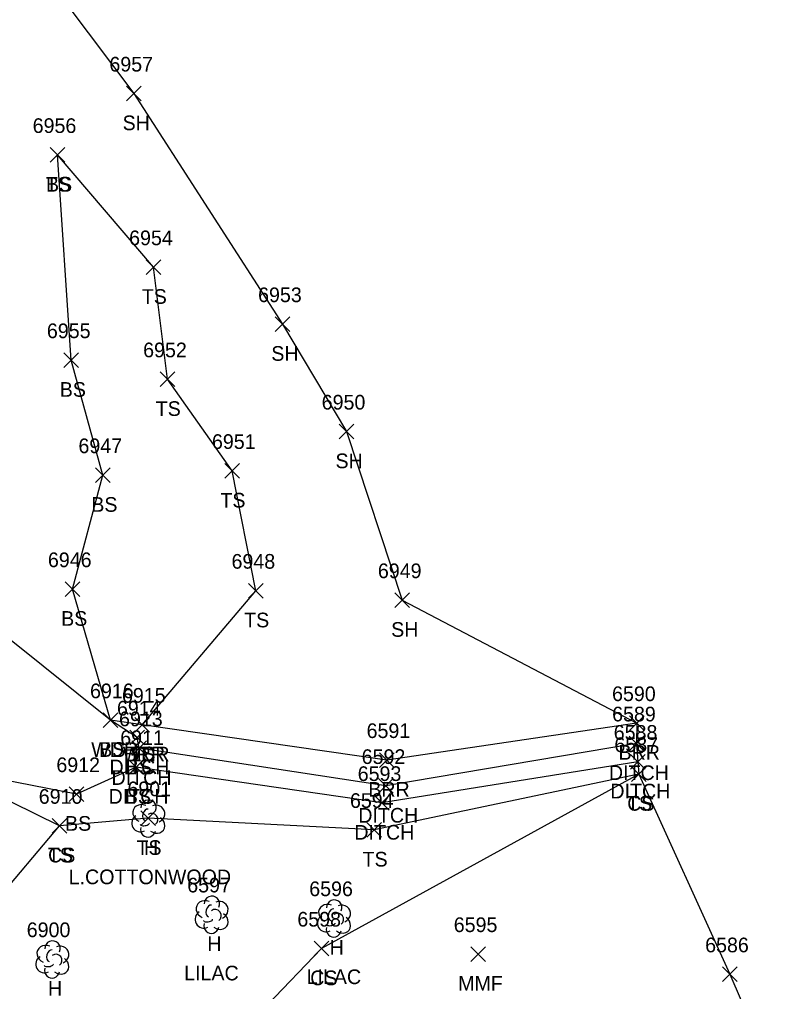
# Model space of a CAD drawing. Extents: x 1439173 to 1457902, y 641926 to 659889.
# Drawn here: x 1448918.5 to 1449022.8, y 643813.5 to 643946.2 of the extents above; entities that cross this region are included whole.
import ezdxf

# ---------------------------------------------------------------- set-up
doc = ezdxf.new("R2010")
doc.units = 0
for name, color, linetype in [('D_A', 7, 'Continuous'), ('D_I', 7, 'Continuous'), ('D_TIC', 7, 'Continuous'), ('DD', 7, 'Continuous'), ('L_A', 7, 'Continuous'), ('L_C', 7, 'Continuous'), ('L_I', 7, 'Continuous'), ('L_TIC', 7, 'Continuous'), ('LABL', 7, 'Continuous'), ('LAWA', 7, 'Continuous'), ('LELB', 7, 'Continuous'), ('LSOGP', 7, 'Continuous'), ('LTD', 7, 'Continuous')]:
    doc.layers.add(name, color=color, linetype=linetype)

msp = doc.modelspace()

# ---------------------------------------------------------------- linework, layer by layer
at = {"layer": 'D_TIC'}
for points in [[(1448933.52, 643847.19), (1448935.52, 643849.19)], [(1448935.52, 643847.19), (1448933.52, 643849.19)], [(1448933.8, 643845.74), (1448935.8, 643847.74)], [(1448935.8, 643845.74), (1448933.8, 643847.74)], [(1449001.59, 643846.4), (1449003.59, 643848.4)], [(1449003.59, 643846.4), (1449001.59, 643848.4)], [(1448933.39, 643843.17), (1448935.39, 643845.17)], [(1448935.39, 643843.17), (1448933.39, 643845.17)], [(1449001.79, 643843.89), (1449003.79, 643845.89)], [(1449003.79, 643843.89), (1449001.79, 643845.89)], [(1448967.43, 643840.59), (1448969.43, 643842.59)], [(1448969.43, 643840.59), (1448967.43, 643842.59)], [(1448966.89, 643838.27), (1448968.89, 643840.27)], [(1448968.89, 643838.27), (1448966.89, 643840.27)]]:
    msp.add_lwpolyline(points, dxfattribs=at)
at = {"layer": 'DD'}
for points in [[(1449002.59, 643847.4), (1448968.43, 643841.59), (1448934.8, 643846.74), (1448934.52, 643848.19)], [(1449002.79, 643844.89), (1448967.89, 643839.27), (1448934.39, 643844.17)]]:
    msp.add_lwpolyline(points, dxfattribs=at)
at = {"layer": 'L_TIC'}
for points in [[(1448933.05, 643935.05), (1448935.05, 643937.05)], [(1448935.05, 643935.05), (1448933.05, 643937.05)], [(1448922.65, 643926.67), (1448924.65, 643928.67)], [(1448924.65, 643926.67), (1448922.65, 643928.67)], [(1448922.65, 643926.67), (1448924.65, 643928.67)], [(1448924.65, 643926.67), (1448922.65, 643928.67)], [(1448935.74, 643911.36), (1448937.74, 643913.36)], [(1448937.74, 643911.36), (1448935.74, 643913.36)], [(1448953.32, 643903.59), (1448955.32, 643905.59)], [(1448955.32, 643903.59), (1448953.32, 643905.59)], [(1448924.53, 643898.68), (1448926.53, 643900.68)], [(1448926.53, 643898.68), (1448924.53, 643900.68)], [(1448937.64, 643896.07), (1448939.64, 643898.07)], [(1448939.64, 643896.07), (1448937.64, 643898.07)], [(1448962.07, 643888.94), (1448964.07, 643890.94)], [(1448964.07, 643888.94), (1448962.07, 643890.94)], [(1448928.83, 643882.99), (1448930.83, 643884.99)], [(1448930.83, 643882.99), (1448928.83, 643884.99)], [(1448946.46, 643883.57), (1448948.46, 643885.57)], [(1448948.46, 643883.57), (1448946.46, 643885.57)], [(1448924.72, 643867.44), (1448926.72, 643869.44)], [(1448926.72, 643867.44), (1448924.72, 643869.44)], [(1448949.7, 643867.23), (1448951.7, 643869.23)], [(1448951.7, 643867.23), (1448949.7, 643869.23)], [(1448969.66, 643865.94), (1448971.66, 643867.94)], [(1448971.66, 643865.94), (1448969.66, 643867.94)], [(1448929.89, 643849.56), (1448931.89, 643851.56)], [(1448931.89, 643849.56), (1448929.89, 643851.56)], [(1448929.89, 643849.56), (1448931.89, 643851.56)], [(1448931.89, 643849.56), (1448929.89, 643851.56)], [(1448934.19, 643848.95), (1448936.19, 643850.95)], [(1448936.19, 643848.95), (1448934.19, 643850.95)], [(1448934.19, 643848.95), (1448936.19, 643850.95)], [(1448936.19, 643848.95), (1448934.19, 643850.95)], [(1448934.19, 643848.95), (1448936.19, 643850.95)], [(1448936.19, 643848.95), (1448934.19, 643850.95)], [(1449001.65, 643849.17), (1449003.65, 643851.17)], [(1449003.65, 643849.17), (1449001.65, 643851.17)], [(1448933.52, 643847.19), (1448935.52, 643849.19)], [(1448935.52, 643847.19), (1448933.52, 643849.19)], [(1448967.54, 643844.13), (1448969.54, 643846.13)], [(1448969.54, 643844.13), (1448967.54, 643846.13)], [(1448933.39, 643843.17), (1448935.39, 643845.17)], [(1448935.39, 643843.17), (1448933.39, 643845.17)], [(1449001.89, 643842.22), (1449003.89, 643844.22)], [(1449003.89, 643842.22), (1449001.89, 643844.22)], [(1449001.89, 643842.22), (1449003.89, 643844.22)], [(1449003.89, 643842.22), (1449001.89, 643844.22)], [(1448925.25, 643839.48), (1448927.25, 643841.48)], [(1448927.25, 643839.48), (1448925.25, 643841.48)], [(1448935.02, 643836.19), (1448937.02, 643838.19)], [(1448937.02, 643836.19), (1448935.02, 643838.19)], [(1448922.94, 643835.16), (1448924.94, 643837.16)], [(1448924.94, 643835.16), (1448922.94, 643837.16)], [(1448922.94, 643835.16), (1448924.94, 643837.16)], [(1448924.94, 643835.16), (1448922.94, 643837.16)], [(1448965.84, 643834.6), (1448967.84, 643836.6)], [(1448967.84, 643834.6), (1448965.84, 643836.6)], [(1448958.67, 643818.41), (1448960.67, 643820.41)], [(1448960.67, 643818.41), (1448958.67, 643820.41)], [(1448979.99, 643817.66), (1448981.99, 643819.66)], [(1448981.99, 643817.66), (1448979.99, 643819.66)], [(1449014.32, 643814.9), (1449016.32, 643816.9)], [(1449016.32, 643814.9), (1449014.32, 643816.9)]]:
    msp.add_lwpolyline(points, dxfattribs=at)
at = {"layer": 'LABL'}
msp.add_lwpolyline([(1449002.65, 643850.17), (1448968.54, 643845.13), (1448935.19, 643849.95)], dxfattribs=at)
at = {"layer": 'LAWA'}
msp.add_lwpolyline([(1448935.19, 643849.95), (1448930.89, 643850.56), (1448912.47, 643865.31), (1448901.69, 643872.66), (1448893.6, 643872.01), (1448887.66, 643878.9), (1448880.15, 643880.34), (1448877.43, 643885.56), (1448873.12, 643888.69), (1448872.18, 643891.06), (1448868.85, 643895.5), (1448865.46, 643900.53), (1448866.99, 643904.37), (1448875.78, 643920.4), (1448875.62, 643935.58), (1448881.79, 643957.41), (1448868.1, 643977.7), (1448859.21, 644002.85), (1448858.88, 644027.76), (1448856.91, 644066.77)], dxfattribs=at)
at = {"layer": 'LELB'}
for points in [[(1448934.52, 643848.19), (1448930.89, 643850.56), (1448925.72, 643868.44), (1448929.83, 643883.99), (1448925.53, 643899.68), (1448923.65, 643927.67)], [(1448935.19, 643849.95), (1448950.7, 643868.23), (1448947.46, 643884.57), (1448938.64, 643897.07), (1448936.74, 643912.36), (1448923.65, 643927.67)], [(1448934.39, 643844.17), (1448926.25, 643840.48), (1448907.86, 643844.08), (1448898.14, 643842.94), (1448892.2, 643837.36)], [(1449002.89, 643843.22), (1448966.84, 643835.6), (1448936.02, 643837.19), (1448923.94, 643836.16), (1448907.86, 643844.08), (1448900.34, 643838.29), (1448899.79, 643830.63), (1448893.68, 643829.16)], [(1449002.89, 643843.22), (1448959.67, 643819.41), (1448944.82, 643803.96), (1448938.16, 643798.4)], [(1448895.29, 643770.7), (1448906.9, 643793.87), (1448905.19, 643812.2), (1448914.92, 643825.49), (1448923.94, 643836.16)]]:
    msp.add_lwpolyline(points, dxfattribs=at)
at = {"layer": 'LSOGP'}
msp.add_lwpolyline([(1448856.91, 644066.77), (1448858.88, 644027.77), (1448883.72, 643997.52), (1448895.03, 643979.77), (1448895.93, 643978.85), (1448899.57, 643975.95), (1448900.3, 643975.15), (1448918.59, 643956.71), (1448934.05, 643936.05), (1448954.32, 643904.59), (1448963.08, 643889.95), (1448970.66, 643866.94), (1449002.65, 643850.17), (1449002.59, 643847.4), (1449002.79, 643844.89), (1449002.89, 643843.22), (1449015.32, 643815.9), (1449022.77, 643798.58)], dxfattribs=at)
at = {"layer": 'LTD'}
for p, q in [((1448936.02, 643837.19), (1448936.02, 643837.19)), ((1448936.02, 643837.19), (1448936.02, 643837.19)), ((1448944.65, 643824.07), (1448944.65, 643824.07)), ((1448944.65, 643824.07), (1448944.65, 643824.07)), ((1448961.34, 643823.56), (1448961.34, 643823.56)), ((1448961.34, 643823.56), (1448961.34, 643823.56)), ((1448922.94, 643817.97), (1448922.94, 643817.97)), ((1448922.94, 643817.97), (1448922.94, 643817.97))]:
    msp.add_line(p, q, dxfattribs=at)
for centre in [(1448936.07, 643838.63), (1448944.7, 643825.51), (1448961.39, 643825), (1448922.99, 643819.41)]:
    msp.add_arc(centre, 1.05, 335.5272, 180.9563, dxfattribs=at)
for centre, major_axis, ratio, start_param, end_param in [((1448935.23, 643837.86), (1.21, -0.51), 0.895232, 1.570796, 4.712389), ((1448935.81, 643837.65), (-0.208, -0.792), 0.645439, 3.141593, 6.283185), ((1448937.06, 643837.78), (-1.14, -0.48), 0.949671, 1.570796, 4.712389), ((1448934.94, 643836.49), (0.58, -1.04), 0.959034, 3.141593, 6.283185), ((1448936.52, 643837.03), (-0.5, 0.667), 0.989748, 3.141593, 6.283185), ((1448937.02, 643836.36), (-1.09, 0.79), 0.841452, 1.570796, 4.712389), ((1448936.02, 643835.69), (0.26, 1.06), 0.942809, 1.570796, 4.712389), ((1448935.56, 643836.44), (-0.625, -0.083), 0.423636, 0, 3.141593), ((1448943.86, 643824.74), (1.21, -0.51), 0.895232, 1.570796, 4.712389), ((1448944.44, 643824.53), (-0.208, -0.792), 0.645439, 3.141593, 6.283185), ((1448945.69, 643824.66), (-1.14, -0.48), 0.949671, 1.570796, 4.712389), ((1448960.55, 643824.23), (1.21, -0.51), 0.895232, 1.570796, 4.712389), ((1448962.38, 643824.15), (-1.14, -0.48), 0.949671, 1.570796, 4.712389), ((1448943.57, 643823.37), (0.58, -1.04), 0.959034, 3.141593, 6.283185), ((1448945.15, 643823.91), (-0.5, 0.667), 0.989748, 3.141593, 6.283185), ((1448945.65, 643823.24), (-1.09, 0.79), 0.841452, 1.570796, 4.712389), ((1448960.26, 643822.85), (0.58, -1.04), 0.959034, 3.141593, 6.283185), ((1448961.13, 643824.02), (-0.208, -0.792), 0.645439, 3.141593, 6.283185), ((1448961.84, 643823.4), (-0.5, 0.667), 0.989748, 3.141593, 6.283185), ((1448962.34, 643822.73), (-1.09, 0.79), 0.841452, 1.570796, 4.712389), ((1448944.65, 643822.57), (0.26, 1.06), 0.942809, 1.570796, 4.712389), ((1448944.19, 643823.32), (-0.625, -0.083), 0.423636, 0, 3.141593), ((1448961.34, 643822.06), (0.26, 1.06), 0.942809, 1.570796, 4.712389), ((1448960.88, 643822.81), (-0.625, -0.083), 0.423636, 0, 3.141593), ((1448922.15, 643818.64), (1.21, -0.51), 0.895232, 1.570796, 4.712389), ((1448923.98, 643818.56), (-1.14, -0.48), 0.949671, 1.570796, 4.712389), ((1448921.86, 643817.26), (0.58, -1.04), 0.959034, 3.141593, 6.283185), ((1448922.73, 643818.43), (-0.208, -0.792), 0.645439, 3.141593, 6.283185), ((1448923.44, 643817.81), (-0.5, 0.667), 0.989748, 3.141593, 6.283185), ((1448922.48, 643817.22), (-0.625, -0.083), 0.423636, 0, 3.141593), ((1448923.94, 643817.14), (-1.09, 0.79), 0.841452, 1.570796, 4.712389), ((1448922.94, 643816.47), (0.26, 1.06), 0.942809, 1.570796, 4.712389)]:
    msp.add_ellipse(centre, major_axis=major_axis, ratio=ratio, start_param=start_param, end_param=end_param, dxfattribs=at)

# ---------------------------------------------------------------- texts
at = {"layer": 'D_A'}
for p in [(1448930.75, 643843.19), (1448931.03, 643841.74), (1448998.83, 643842.4), (1448930.63, 643839.17), (1448999.03, 643839.89), (1448964.67, 643836.59), (1448964.13, 643834.27)]:
    msp.add_text('DITCH', height=2, dxfattribs=at).set_placement(p)
at = {"layer": 'D_I'}
for s, p in [('6914', (1448931.77, 643851.19)), ('6913', (1448932.06, 643849.74)), ('6589', (1448999.27, 643850.4)), ('6911', (1448932.22, 643847.17)), ('6588', (1448999.49, 643847.89)), ('6592', (1448965.13, 643844.59)), ('6593', (1448964.59, 643842.27))]:
    msp.add_text(s, height=2, dxfattribs=at).set_placement(p)
at = {"layer": 'L_A'}
for s, p in [('SH', (1448932.54, 643931.05)), ('TS', (1448922.06, 643922.67)), ('BS', (1448922.09, 643922.67)), ('TS', (1448935.15, 643907.36)), ('SH', (1448952.81, 643899.59)), ('BS', (1448923.97, 643894.68)), ('TS', (1448937.05, 643892.07)), ('SH', (1448961.56, 643884.94)), ('BS', (1448928.27, 643878.99)), ('TS', (1448945.87, 643879.57)), ('BS', (1448924.16, 643863.44)), ('TS', (1448949.11, 643863.23)), ('SH', (1448969.15, 643861.94)), ('WDR', (1448928.26, 643845.56)), ('BS', (1448929.34, 643845.56)), ('WDR', (1448932.55, 643844.95)), ('BRR', (1448932.68, 643844.95)), ('TS', (1448933.6, 643844.95)), ('BRR', (1449000.14, 643845.17)), ('BS', (1448932.96, 643843.19)), ('BS', (1448932.84, 643839.17)), ('BRR', (1448966.03, 643840.13)), ('TS', (1449001.3, 643838.22)), ('CS', (1449001.33, 643838.22)), ('BS', (1448924.69, 643835.48)), ('TS', (1448934.43, 643832.19)), ('H', (1448935.45, 643832.19)), ('TS', (1448922.35, 643831.16)), ('CS', (1448922.38, 643831.16)), ('TS', (1448965.25, 643830.6)), ('H', (1448944.09, 643819.07)), ('H', (1448960.77, 643818.56)), ('CS', (1448958.11, 643814.41)), ('MMF', (1448978.28, 643813.66)), ('H', (1448922.37, 643812.97))]:
    msp.add_text(s, height=2, dxfattribs=at).set_placement(p)
at = {"layer": 'L_C'}
for s, p in [('L.COTTONWOOD', (1448925.19, 643828.19)), ('LILAC', (1448940.93, 643815.07)), ('LILAC', (1448957.62, 643814.56))]:
    msp.add_text(s, height=2, dxfattribs=at).set_placement(p)
at = {"layer": 'L_I'}
for s, p in [('6957', (1448930.74, 643939.05)), ('6956', (1448920.28, 643930.67)), ('6956', (1448920.28, 643930.67)), ('6954', (1448933.43, 643915.36)), ('6953', (1448951.01, 643907.59)), ('6955', (1448922.22, 643902.68)), ('6952', (1448935.34, 643900.07)), ('6950', (1448959.68, 643892.94)), ('6947', (1448926.52, 643886.99)), ('6951', (1448944.72, 643887.57)), ('6946', (1448922.36, 643871.44)), ('6948', (1448947.39, 643871.23)), ('6949', (1448967.34, 643869.94)), ('6916', (1448928.1, 643853.56)), ('6916', (1448928.1, 643853.56)), ('6915', (1448932.45, 643852.95)), ('6915', (1448932.45, 643852.95)), ('6915', (1448932.45, 643852.95)), ('6590', (1448999.26, 643853.17)), ('6914', (1448931.77, 643851.19)), ('6591', (1448965.8, 643848.13)), ('6911', (1448932.22, 643847.17)), ('6587', (1448999.58, 643846.22)), ('6587', (1448999.58, 643846.22)), ('6912', (1448923.51, 643843.48)), ('6901', (1448933.2, 643840.19)), ('6901', (1448933.2, 643840.19)), ('6910', (1448921.11, 643839.16)), ('6910', (1448921.11, 643839.16)), ('6594', (1448963.53, 643838.6)), ('6597', (1448941.35, 643827.07)), ('6596', (1448957.98, 643826.56)), ('6598', (1448956.36, 643822.41)), ('6595', (1448977.68, 643821.66)), ('6900', (1448919.47, 643820.97)), ('6586', (1449011.95, 643818.9))]:
    msp.add_text(s, height=2, dxfattribs=at).set_placement(p)

doc.saveas('drawing.dxf')
